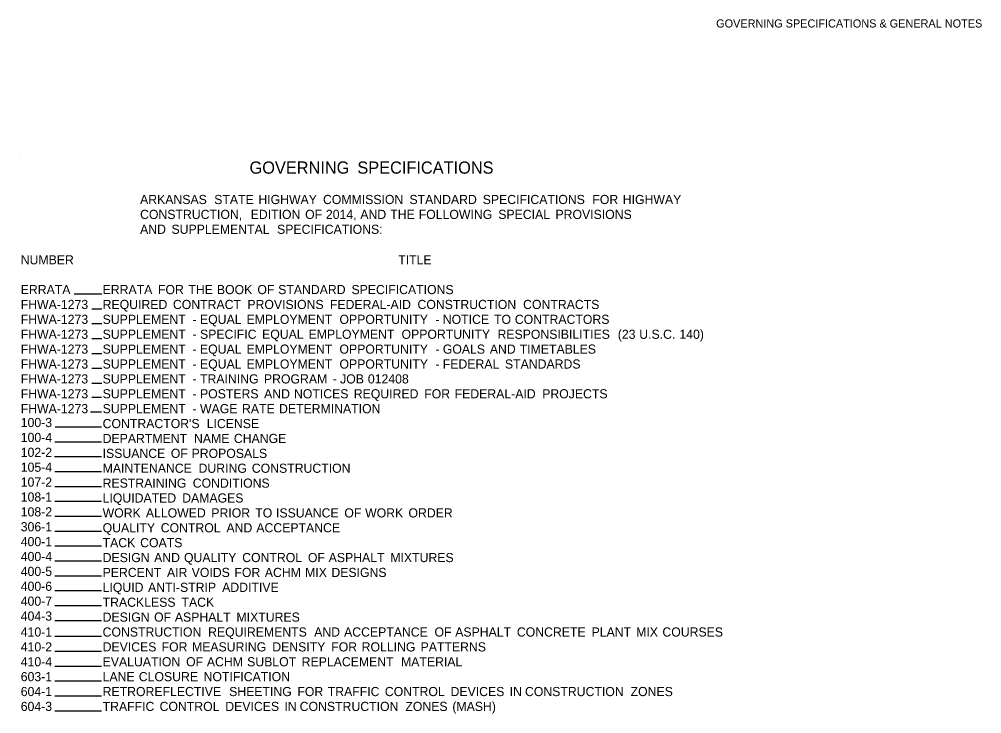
# Model space of a CAD drawing. Extents: x 1930579 to 1932218, y 596452 to 599494.
# Drawn here: x 1931524 to 1932218, y 598994 to 599494 of the extents above; entities that cross this region are included whole.
import ezdxf

# ---------------------------------------------------------------- set-up
doc = ezdxf.new("R2010")
doc.units = 0
for name, color, linetype in [('Default', 7, 'Continuous'), ('R_Border', 7, 'Continuous'), ('S_AREA_CALC', 7, 'Continuous')]:
    doc.layers.add(name, color=color, linetype=linetype)

msp = doc.modelspace()

# ---------------------------------------------------------------- linework, layer by layer
at = {"layer": 'R_Border'}
for p, q in [((1931524.27, 599395.37), (1931524.27, 599395.37)), ((1931563.85, 599296.07), (1931583.71, 599296.07)), ((1931576.5, 599285.34), (1931583.71, 599285.34)), ((1931576.5, 599274.62), (1931583.71, 599274.62)), ((1931576.5, 599263.89), (1931583.71, 599263.89)), ((1931576.5, 599253.17), (1931583.71, 599253.17)), ((1931576.5, 599242.44), (1931583.71, 599242.44)), ((1931576.5, 599231.72), (1931583.71, 599231.72)), ((1931576.5, 599221.73), (1931583.53, 599221.73)), ((1931575.64, 599211.01), (1931583.53, 599211.01)), ((1931550.12, 599200.28), (1931583.53, 599200.28)), ((1931549.9, 599189.56), (1931583.53, 599189.56)), ((1931549.66, 599178.83), (1931583.53, 599178.83)), ((1931549.9, 599168.11), (1931583.53, 599168.11)), ((1931549.9, 599157.38), (1931583.53, 599157.38)), ((1931549.9, 599146.66), (1931583.53, 599146.66)), ((1931549.9, 599135.93), (1931583.53, 599135.93)), ((1931549.9, 599125.21), (1931583.53, 599125.21)), ((1931549.9, 599114.48), (1931583.53, 599114.48)), ((1931549.9, 599103.76), (1931583.53, 599103.76)), ((1931549.9, 599093.03), (1931583.53, 599093.03)), ((1931549.9, 599082.31), (1931583.53, 599082.31)), ((1931549.9, 599071.58), (1931583.53, 599071.58)), ((1931549.9, 599060.86), (1931583.53, 599060.86)), ((1931549.9, 599049.39), (1931583.53, 599049.39)), ((1931549.9, 599038.67), (1931583.53, 599038.67)), ((1931549.9, 599027.94), (1931583.53, 599027.94)), ((1931549.9, 599017.22), (1931583.53, 599017.22)), ((1931549.9, 599006.49), (1931583.53, 599006.49)), ((1931549.9, 598995.77), (1931583.53, 598995.77))]:
    msp.add_line(p, q, dxfattribs=at)

# ---------------------------------------------------------------- texts
at = {"layer": 'Default'}
for s, height, p in [('GOVERNING', 8.8, (1931690.13, 599382.66)), (' SPECIFICATIONS', 8.8, (1931764.54, 599382.66)), ('           ARKANSAS', 6.6, (1931584.33, 599360.77)), (' STATE', 6.6, (1931662.24, 599360.77)), (' HIGHWAY', 6.6, (1931694.04, 599360.77)), (' COMMISSION', 6.6, (1931740.59, 599360.77)), (' STANDARD', 6.6, (1931802.85, 599360.77)), (' SPECIFICATIONS', 6.6, (1931855.65, 599360.77)), (' FOR', 6.6, (1931934.59, 599360.77)), (' HIGHWAY', 6.6, (1931956.5, 599360.77)), ('           CONSTRUCTION,', 6.6, (1931584.33, 599350.04)), (' EDITION', 6.6, (1931688.52, 599350.04)), (' OF', 6.6, (1931727.73, 599350.04)), (' 2014,', 6.6, (1931742.68, 599350.04)), (' AND', 6.6, (1931767.48, 599350.04)), (' THE', 6.6, (1931789.02, 599350.04)), (' FOLLOWING', 6.6, (1931809.54, 599350.04)), (' SPECIAL', 6.6, (1931866.85, 599350.04)), (' PROVISIONS', 6.6, (1931908.04, 599350.04)), ('           AND', 6.6, (1931584.33, 599339.32)), (' SUPPLEMENTAL', 6.6, (1931631.47, 599339.32)), (' SPECIFICATIONS:', 6.6, (1931707.51, 599339.32)), ('NUMBER', 6.6, (1931525.34, 599317.33)), ('TITLE', 6.6, (1931797.24, 599317.33)), ('ERRATA', 6.6, (1931525.34, 599295.88)), ('ERRATA', 6.6, (1931584.33, 599295.88)), (' FOR', 6.6, (1931621.75, 599295.88)), (' THE', 6.6, (1931643.66, 599295.88)), (' BOOK', 6.6, (1931664.17, 599295.88)), (' OF', 6.6, (1931693.36, 599295.88)), (' STANDARD', 6.6, (1931708.31, 599295.88)), (' SPECIFICATIONS', 6.6, (1931761.11, 599295.88)), ('FHWA-1273', 6.6, (1931525.34, 599285.15)), ('REQUIRED', 6.6, (1931584.33, 599285.15)), (' CONTRACT', 6.6, (1931632.51, 599285.15)), (' PROVISIONS', 6.6, (1931686.12, 599285.15)), (' FEDERAL-AID', 6.6, (1931745.6, 599285.15)), (' CONSTRUCTION', 6.6, (1931808.65, 599285.15)), (' CONTRACTS', 6.6, (1931884.74, 599285.15)), ('FHWA-1273', 6.6, (1931525.34, 599274.43)), ('SUPPLEMENT', 6.6, (1931584.33, 599274.43)), (' EQUAL', 6.6, (1931652.01, 599274.43)), (' EMPLOYMENT', 6.6, (1931685.51, 599274.43)), (' OPPORTUNITY', 6.6, (1931752.45, 599274.43)), (' NOTICE', 6.6, (1931826.89, 599274.43)), (' TO', 6.6, (1931863.8, 599274.43)), (' CONTRACTORS', 6.6, (1931878.76, 599274.43)), (' -', 6.6, (1931646.66, 599274.43)), (' -', 6.6, (1931821.55, 599274.43)), (' (23', 6.6, (1931952.92, 599263.7)), (' 140)', 6.6, (1931997.29, 599263.7)), ('FHWA-1273', 6.6, (1931525.34, 599263.7)), ('SUPPLEMENT', 6.6, (1931584.33, 599263.7)), (' -', 6.6, (1931646.66, 599263.7)), (' SPECIFIC', 6.6, (1931652.01, 599263.7)), (' EQUAL', 6.6, (1931696.73, 599263.7)), (' EMPLOYMENT', 6.6, (1931730.23, 599263.7)), (' OPPORTUNITY', 6.6, (1931797.17, 599263.7)), (' RESPONSIBILITIES', 6.6, (1931866.28, 599263.7)), (' U.S.C.', 6.6, (1931968.38, 599263.7)), ('FHWA-1273', 6.6, (1931525.34, 599252.98)), ('SUPPLEMENT', 6.6, (1931584.33, 599252.98)), (' EQUAL', 6.6, (1931652.01, 599252.98)), (' EMPLOYMENT', 6.6, (1931685.51, 599252.98)), (' OPPORTUNITY', 6.6, (1931752.45, 599252.98)), (' GOALS', 6.6, (1931826.89, 599252.98)), (' AND', 6.6, (1931860.75, 599252.98)), (' TIMETABLES', 6.6, (1931882.29, 599252.98)), (' -', 6.6, (1931646.66, 599252.98)), (' -', 6.6, (1931821.55, 599252.98)), ('FHWA-1273', 6.6, (1931525.34, 599242.25)), ('SUPPLEMENT', 6.6, (1931584.33, 599242.25)), (' -', 6.6, (1931646.66, 599242.25)), (' EQUAL', 6.6, (1931652.01, 599242.25)), (' EMPLOYMENT', 6.6, (1931685.51, 599242.25)), (' OPPORTUNITY', 6.6, (1931752.45, 599242.25)), (' -', 6.6, (1931821.55, 599242.25)), (' FEDERAL', 6.6, (1931826.89, 599242.25)), (' STANDARDS', 6.6, (1931871.66, 599242.25)), ('FHWA-1273', 6.6, (1931525.34, 599231.53)), ('SUPPLEMENT', 6.6, (1931584.33, 599231.53)), (' TRAINING', 6.6, (1931652.01, 599231.53)), (' PROGRAM', 6.6, (1931698.05, 599231.53)), (' JOB', 6.6, (1931752.91, 599231.53)), (' 012408', 6.6, (1931772.92, 599231.53)), (' -', 6.6, (1931646.66, 599231.53)), (' -', 6.6, (1931747.57, 599231.53)), ('FHWA-1273', 6.6, (1931525.34, 599220.8)), ('SUPPLEMENT', 6.6, (1931584.33, 599220.8)), (' -', 6.6, (1931646.66, 599220.8)), (' POSTERS', 6.6, (1931652.01, 599220.8)), (' AND', 6.6, (1931698.16, 599220.8)), (' NOTICES', 6.6, (1931719.7, 599220.8)), (' REQUIRED', 6.6, (1931762.77, 599220.8)), (' FOR', 6.6, (1931813.52, 599220.8)), (' FEDERAL-AID', 6.6, (1931835.42, 599220.8)), (' PROJECTS', 6.6, (1931898.47, 599220.8)), ('FHWA-1273', 6.6, (1931525.34, 599210.08)), ('SUPPLEMENT', 6.6, (1931584.33, 599210.08)), (' WAGE', 6.6, (1931652.01, 599210.08)), (' RATE', 6.6, (1931682.26, 599210.08)), (' DETERMINATION', 6.6, (1931708.92, 599210.08)), (' -', 6.6, (1931646.66, 599210.08)), ('100-3', 6.6, (1931525.34, 599200.1)), ("CONTRACTOR'S", 6.6, (1931584.33, 599199.35)), (' LICENSE', 6.6, (1931656.83, 599199.35)), ('100-4', 6.6, (1931525.34, 599189.37)), ('DEPARTMENT', 6.6, (1931584.33, 599188.63)), (' NAME', 6.6, (1931647.68, 599188.63)), (' CHANGE', 6.6, (1931676.39, 599188.63)), ('102-2', 6.6, (1931525.34, 599178.65)), ('ISSUANCE', 6.6, (1931584.33, 599177.9)), (' OF', 6.6, (1931630.98, 599177.9)), (' PROPOSALS', 6.6, (1931645.93, 599177.9)), ('105-4', 6.6, (1931525.34, 599167.92)), ('MAINTENANCE', 6.6, (1931584.33, 599167.18)), (' DURING', 6.6, (1931650.96, 599167.18)), (' CONSTRUCTION', 6.6, (1931689.32, 599167.18)), ('107-2', 6.6, (1931525.34, 599157.2)), ('RESTRAINING', 6.6, (1931584.33, 599156.45)), (' CONDITIONS', 6.6, (1931646.78, 599156.45)), ('108-1', 6.6, (1931525.34, 599146.47)), ('LIQUIDATED', 6.6, (1931584.33, 599145.73)), (' DAMAGES', 6.6, (1931639.17, 599145.73)), ('108-2', 6.6, (1931525.34, 599135.75)), ('WORK', 6.6, (1931584.33, 599135)), (' ALLOWED', 6.6, (1931613, 599135)), (' PRIOR', 6.6, (1931660.16, 599135)), (' TO', 6.6, (1931691.8, 599135)), (' ISSUANCE', 6.6, (1931706.75, 599135)), (' OF', 6.6, (1931755.97, 599135)), (' WORK', 6.6, (1931770.92, 599135)), (' ORDER', 6.6, (1931802.15, 599135)), ('306-1', 6.6, (1931525.34, 599125.02)), ('QUALITY', 6.6, (1931584.33, 599124.28)), (' CONTROL', 6.6, (1931623.72, 599124.28)), (' AND', 6.6, (1931671.04, 599124.28)), (' ACCEPTANCE', 6.6, (1931692.58, 599124.28)), ('400-1', 6.6, (1931525.34, 599114.3)), ('TACK', 6.6, (1931584.33, 599113.55)), (' COATS', 6.6, (1931608.91, 599113.55)), ('400-4', 6.6, (1931525.34, 599103.57)), ('DESIGN', 6.6, (1931584.33, 599102.83)), (' AND', 6.6, (1931618.93, 599102.83)), (' QUALITY', 6.6, (1931640.47, 599102.83)), (' CONTROL', 6.6, (1931682.42, 599102.83)), (' OF', 6.6, (1931729.74, 599102.83)), (' ASPHALT', 6.6, (1931744.69, 599102.83)), (' MIXTURES', 6.6, (1931789.09, 599102.83)), ('400-5', 6.6, (1931525.34, 599092.85)), ('PERCENT', 6.6, (1931584.33, 599092.1)), (' AIR', 6.6, (1931628.21, 599092.1)), (' VOIDS', 6.6, (1931646.02, 599092.1)), (' FOR', 6.6, (1931676.8, 599092.1)), (' ACHM', 6.6, (1931698.7, 599092.1)), (' MIX', 6.6, (1931727.72, 599092.1)), (' DESIGNS', 6.6, (1931746.62, 599092.1)), ('400-6', 6.6, (1931525.34, 599082.12)), ('LIQUID', 6.6, (1931584.33, 599081.38)), (' ANTI-STRIP', 6.6, (1931614.58, 599081.38)), (' ADDITIVE', 6.6, (1931667.97, 599081.38)), ('400-7', 6.6, (1931525.34, 599071.4)), ('TRACKLESS', 6.6, (1931584.33, 599070.65)), (' TACK', 6.6, (1931638.69, 599070.65)), ('404-3', 6.6, (1931525.34, 599060.67)), ('DESIGN', 6.6, (1931584.33, 599059.93)), (' OF', 6.6, (1931618.93, 599059.93)), (' ASPHALT', 6.6, (1931633.88, 599059.93)), (' MIXTURES', 6.6, (1931678.28, 599059.93)), ('410-1', 6.6, (1931525.34, 599049.2)), ('CONSTRUCTION', 6.6, (1931584.33, 599049.2)), (' REQUIREMENTS', 6.6, (1931657.86, 599049.2)), (' AND', 6.6, (1931734.24, 599049.2)), (' ACCEPTANCE', 6.6, (1931755.78, 599049.2)), (' OF', 6.6, (1931820.89, 599049.2)), (' ASPHALT', 6.6, (1931835.83, 599049.2)), (' CONCRETE', 6.6, (1931880.24, 599049.2)), (' PLANT', 6.6, (1931934.06, 599049.2)), (' MIX', 6.6, (1931966.16, 599049.2)), (' COURSES', 6.6, (1931985.05, 599049.2)), ('410-2', 6.6, (1931525.34, 599038.48)), ('DEVICES', 6.6, (1931584.33, 599038.48)), (' FOR', 6.6, (1931624.33, 599038.48)), (' MEASURING', 6.6, (1931646.24, 599038.48)), (' DENSITY', 6.6, (1931704.07, 599038.48)), (' FOR', 6.6, (1931746.53, 599038.48)), (' ROLLING', 6.6, (1931768.44, 599038.48)), (' PATTERNS', 6.6, (1931810.9, 599038.48)), ('410-4', 6.6, (1931525.34, 599027.75)), ('EVALUATION', 6.6, (1931584.33, 599027.75)), (' OF', 6.6, (1931642, 599027.75)), (' ACHM', 6.6, (1931656.94, 599027.75)), (' SUBLOT', 6.6, (1931685.96, 599027.75)), (' REPLACEMENT', 6.6, (1931725.24, 599027.75)), (' MATERIAL', 6.6, (1931796.79, 599027.75)), ('603-1', 6.6, (1931525.34, 599017.03)), ('LANE', 6.6, (1931584.33, 599017.03)), (' CLOSURE', 6.6, (1931607.92, 599017.03)), (' NOTIFICATION', 6.6, (1931654.58, 599017.03)), ('604-1', 6.6, (1931525.34, 599006.3)), ('RETROREFLECTIVE', 6.6, (1931584.33, 599006.3)), (' SHEETING', 6.6, (1931673, 599006.3)), (' FOR', 6.6, (1931722.13, 599006.3)), (' TRAFFIC', 6.6, (1931744.03, 599006.3)), (' CONTROL', 6.6, (1931785.16, 599006.3)), (' DEVICES', 6.6, (1931832.48, 599006.3)), (' IN', 6.6, (1931875.05, 599006.3)), (' CONSTRUCTION', 6.6, (1931886.08, 599006.3)), (' ZONES', 6.6, (1931962.17, 599006.3)), ('604-3', 6.6, (1931525.34, 598995.58)), ('TRAFFIC', 6.6, (1931584.33, 598995.58)), (' CONTROL', 6.6, (1931622.9, 598995.58)), (' DEVICES', 6.6, (1931670.22, 598995.58)), (' IN', 6.6, (1931712.79, 598995.58)), (' CONSTRUCTION', 6.6, (1931723.81, 598995.58)), (' ZONES', 6.6, (1931799.91, 598995.58)), (' (MASH)', 6.6, (1931833.76, 598995.58))]:
    msp.add_text(s, height=height, dxfattribs=at).set_placement(p)
at = {"layer": 'S_AREA_CALC'}
msp.add_text('GOVERNING SPECIFICATIONS & GENERAL NOTES', height=5.862, rotation=360, dxfattribs=at).set_placement((1932026.23, 599487.97))

doc.saveas('drawing.dxf')
